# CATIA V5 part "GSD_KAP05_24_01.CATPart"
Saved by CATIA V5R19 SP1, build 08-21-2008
Part number: GSD_BOUNDARY_01
Definition: Beispielmodell für die Funktion Begrenzung / Boundary.
Description: CATIA V5 Flächenmodellierung  Copyright (c) 2009 Maik Hertha IT Consultants
Bounding box of the stored display mesh (mm): x 15.23 to 53.339, y -25.102 to 31.299, z 8.081 to 34.778
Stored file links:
  C:\Users\Maik\CAD Daten\modelle\gsd_buch_uebung\GSD_KAP05_24_01.CATPart
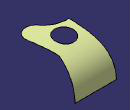
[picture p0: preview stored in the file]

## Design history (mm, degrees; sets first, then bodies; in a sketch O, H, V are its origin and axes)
AxisSystem1 "Absolute Axis System": origin (0, 0, 0), X (1, 0, 0), Y (0, 1, 0), Z (0, 0, 1)
Set1 "Boundary Support"
  Plane1: type Equation, A 1, B 0, C 0, Length 0
  Sketch1 on Plane1, origin (0, 0, 0), H (0, 1, 0), V (0, 0, 1)
    spline S1 through (-33.9513, 34.4754) (-10.135, 34.6383) (25.1, 24.3739) (31.2988, 8.0811)
    curve C1
  Extrude1: Lim1 56, Lim2 -6, Element1 Sketch1.C1, Direction Plane1
  Plane2: type Equation, A 0, B 0, C 1, Length -10
  Sketch2 on Plane2, origin (0, 0, -10), H (-1, 0, 0), V (0, -1, 0)
    line L1 (-53.6424, -32.3162) -> (-47.0606, -10.2368)
    line L2 (-47.0606, -10.2368) -> (-51.7551, 13.6828)
    arc A1 centre (-42.3577, 15.5272) radius 9.5767 from (-51.7551, 13.6828) to (-34.7461, 21.3389) cw
    arc A2 centre (-16.6371, 35.1657) radius 22.7841 from (-34.7461, 21.3389) to (-15.2302, 12.4251) ccw
    line L3 (-15.2302, 12.4251) -> (-15.2302, -32.3162)
    line L4 (-15.2302, -32.3162) -> (-53.6424, -32.3162)
    curve C1
    circle A3 centre (-30.2591, 1.7554) radius 8.7547
    curve C2
    tangency: A1 L2, A2 A1, A3 A1
    vertical: L3 V
    horizontal: L4 H
  Extrude2: Lim1 56, Lim2 -6, Element1 Sketch2.C1, Direction Plane2
  Extrude3: Lim1 56, Lim2 -6, Element1 Sketch2.C2, Direction Plane2
  Split1: ToCut Extrude1, Cutting Extrude2
  Split2 "Boundary Face": ToCut Split1, Cutting Extrude3
Set2 "Whole Face"
  DatumSurface1 "Boundary Face": linked copy from another document
Set3 "Complete "
  DatumSurface2 "Boundary Face": linked copy from another document
Set4 "Point Continuity"
  DatumSurface3 "Boundary Face": linked copy from another document
Set5 "Point Continuity With Limits"
  DatumSurface4 "Boundary Face": linked copy from another document
Set6 "Tangent Continuity"
  DatumSurface5 "Boundary Face": linked copy from another document
Set7 "No Propagation"
  DatumSurface6 "Boundary Face": linked copy from another document
Body1 (main body)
